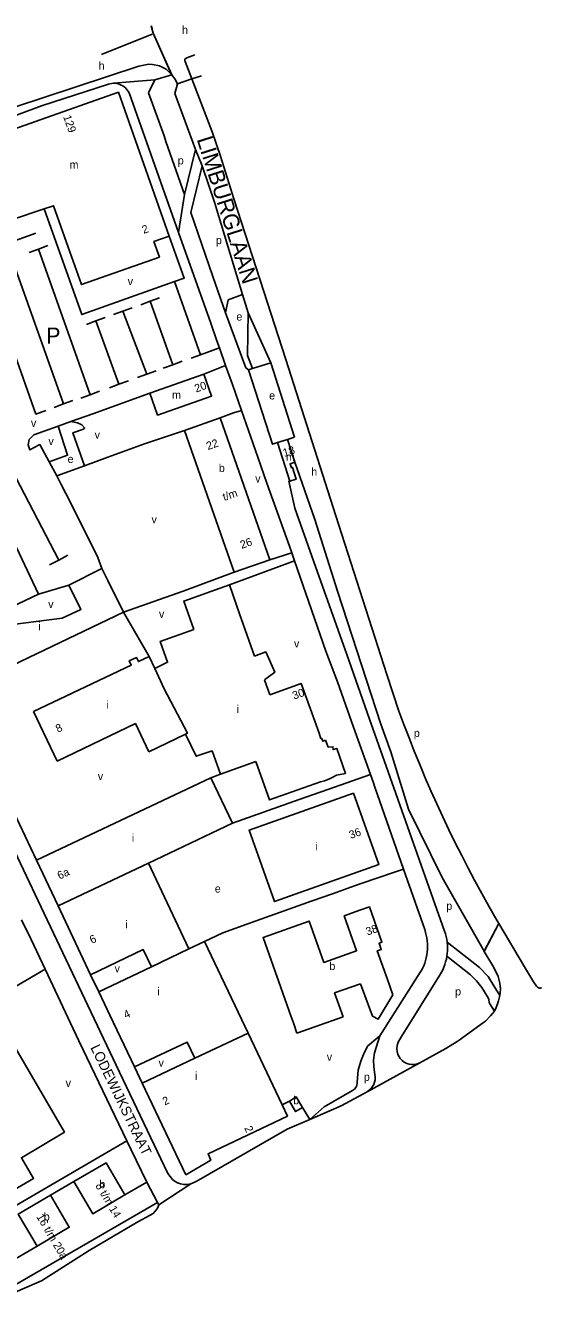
# Model space of a CAD drawing. Extents: x 157699 to 159683, y 381451 to 383293.
# Drawn here: x 159425 to 159683, y 382358 to 382995 of the extents above; entities that cross this region are included whole.
import ezdxf

# ---------------------------------------------------------------- set-up
doc = ezdxf.new("R2010")
doc.units = 0
for name, color, linetype in [('BLT_Basislijn', 7, 'Continuous'), ('BLT_Bebouwing', 7, 'Continuous'), ('BLT_Centroide', 7, 'Continuous'), ('BLT_Huisnummer', 7, 'Continuous'), ('BLT_Huisnummer_reeks', 7, 'Continuous'), ('BLT_Onderverdeling_panden', 7, 'Continuous'), ('BLT_Straatnaam', 7, 'Continuous'), ('BLT_Straatnaam_hoofdweg', 7, 'Continuous'), ('BLT_Tekst_parkeren', 7, 'Continuous'), ('BLT_Vlakafsluiter', 7, 'Continuous')]:
    doc.layers.add(name, color=color, linetype=linetype)

msp = doc.modelspace()

# ---------------------------------------------------------------- linework, layer by layer
at = {"layer": 'BLT_Basislijn'}
for p, q in [((159463.37, 382980.61), (159488.62, 382990.71)), ((159506.02, 382978.92), (159510.05, 382980.42)), ((159505.11, 382977.1), (159508.43, 382968.42)), ((159498.4, 382970.54), (159498.5, 382970.45)), ((159508.43, 382968.42), (159513.39, 382969.92)), ((159508.43, 382968.42), (159518.61, 382941.93)), ((159466.78, 382965.78), (159433.38, 382954.9)), ((159501.88, 382891.65), (159477.18, 382961.35)), ((159486.85, 382961.48), (159494.69, 382939.89)), ((159501.38, 382965.85), (159500.06, 382961.05)), ((159405.59, 382944.56), (159433.38, 382954.9)), ((159494.69, 382939.89), (159495.54, 382937.13)), ((159495.54, 382937.13), (159504.79, 382910.54)), ((159504.79, 382910.54), (159510.28, 382933.07)), ((159507.93, 382901.53), (159513.7, 382924.93)), ((159504.79, 382910.54), (159501.88, 382891.65)), ((159520.31, 382905.05), (159533.82, 382860.61)), ((159507.93, 382901.53), (159519.02, 382869.64)), ((159411.28, 382884.48), (159430.54, 382891.32)), ((159517.97, 382846.23), (159501.88, 382891.65)), ((159431.88, 382883.32), (159436.56, 382885.04)), ((159444.29, 382805.9), (159418.48, 382878.56)), ((159427.2, 382881.61), (159431.88, 382883.32)), ((159457.74, 382810.53), (159431.88, 382883.32)), ((159487.63, 382857.22), (159492.3, 382858.94)), ((159526.75, 382858.01), (159533.82, 382860.61)), ((159533.82, 382860.61), (159536.62, 382851.43)), ((159469.37, 382850.57), (159474.04, 382852.29)), ((159474.04, 382852.29), (159478.72, 382854.01)), ((159485.97, 382820.78), (159474.04, 382852.29)), ((159482.95, 382855.51), (159487.63, 382857.22)), ((159498.93, 382825.49), (159487.63, 382857.22)), ((159526.75, 382858.01), (159525.41, 382851.44)), ((159455.86, 382845.67), (159460.54, 382847.39)), ((159460.54, 382847.39), (159465.21, 382849.1)), ((159472.09, 382815.74), (159460.54, 382847.39)), ((159521.07, 382837.49), (159517.97, 382846.23)), ((159525.41, 382851.44), (159535.47, 382823.87)), ((159512.8, 382830.53), (159522.3, 382834.01)), ((159522.3, 382834.01), (159521.07, 382837.49)), ((159498.93, 382825.49), (159503.61, 382827.21)), ((159508.13, 382828.81), (159512.8, 382830.53)), ((159538.8, 382823.54), (159548.04, 382826.45)), ((159548.04, 382826.45), (159559.89, 382789.26)), ((159481.29, 382819.07), (159485.97, 382820.78)), ((159485.97, 382820.78), (159490.65, 382822.5)), ((159494.26, 382823.78), (159498.93, 382825.49)), ((159514.48, 382820.81), (159525.41, 382825.2)), ((159535.47, 382823.87), (159536.81, 382822.92)), ((159536.81, 382822.92), (159538.8, 382823.54)), ((159467.42, 382814.03), (159472.09, 382815.74)), ((159472.09, 382815.74), (159476.77, 382817.46)), ((159444.29, 382805.9), (159448.97, 382807.61)), ((159453.06, 382808.82), (159457.74, 382810.53)), ((159457.74, 382810.53), (159462.42, 382812.25)), ((159459.06, 382801.01), (159487.53, 382811.25)), ((159439.61, 382804.18), (159444.29, 382805.9)), ((159459.06, 382801.01), (159448.05, 382797.05)), ((159529.37, 382801.41), (159522.67, 382798.96)), ((159529.37, 382801.41), (159533.34, 382802.64)), ((159541.57, 382779.22), (159533.34, 382802.64)), ((159441.63, 382794.74), (159448.05, 382797.05)), ((159504.82, 382792.7), (159484.78, 382785.99)), ((159559.89, 382789.26), (159556.38, 382788.16)), ((159484.78, 382785.99), (159466.45, 382779.24)), ((159414.23, 382781.36), (159441.99, 382727.89)), ((159440.95, 382769.95), (159437.14, 382777.01)), ((159466.45, 382779.24), (159454.82, 382775.01)), ((159546.09, 382766.34), (159541.57, 382779.22)), ((159559.99, 382776.77), (159565.03, 382762.55)), ((159454.82, 382775.01), (159440.95, 382769.95)), ((159547.59, 382762.09), (159546.09, 382766.34)), ((159557.31, 382734.87), (159547.59, 382762.09)), ((159569.57, 382726.97), (159559.93, 382753.88)), ((159580.53, 382750), (159606.02, 382670.74)), ((159547.57, 382728.03), (159558.52, 382731.4)), ((159558.52, 382731.4), (159557.31, 382734.87)), ((159559.87, 382727.51), (159558.52, 382731.4)), ((159441.99, 382727.89), (159437.42, 382725.52)), ((159446.55, 382730.26), (159441.99, 382727.89)), ((159463.57, 382723.62), (159461.58, 382729.21)), ((159559.87, 382727.51), (159527.32, 382715.42)), ((159575.52, 382682.39), (159559.87, 382727.51)), ((159586.01, 382680.69), (159569.57, 382726.97)), ((159529.74, 382721.76), (159504.22, 382712.26)), ((159446.99, 382715.3), (159431.91, 382710.87)), ((159504.22, 382712.26), (159474.33, 382701.74)), ((159603.04, 382645.83), (159581.33, 382712.26)), ((159474.33, 382701.74), (159487.16, 382679.66)), ((159597.38, 382648.39), (159586.01, 382680.69)), ((159606.02, 382670.74), (159612.07, 382652.34)), ((159430.88, 382577.83), (159390.88, 382662.04)), ((159597.8, 382620.63), (159589.42, 382644.27)), ((159518.05, 382619.09), (159522.8, 382620.8)), ((159576.55, 382613.23), (159597.8, 382620.63)), ((159599.29, 382616.45), (159597.8, 382620.63)), ((159599.29, 382616.45), (159600, 382614.42)), ((159562.16, 382608.13), (159576.55, 382613.23)), ((159600, 382614.42), (159614.36, 382573.42)), ((159434.7, 382551.26), (159407.09, 382609.31)), ((159528.82, 382596.4), (159562.16, 382608.13)), ((159593.2, 382566.2), (159609.78, 382571.86)), ((159609.78, 382571.86), (159614.36, 382573.42)), ((159614.36, 382573.42), (159624.96, 382543.14)), ((159634.86, 382542.34), (159623.17, 382575.44)), ((159654.59, 382532.3), (159633.66, 382569.27)), ((159578.81, 382561.1), (159568.61, 382557.48)), ((159568.61, 382557.48), (159535.99, 382545.91)), ((159470.75, 382475.35), (159434.7, 382551.26)), ((159426.63, 382541.3), (159435.12, 382523.3)), ((159654.62, 382532.25), (159654.59, 382532.3)), ((159435.12, 382523.3), (159363.3, 382481.22)), ((159435.12, 382523.3), (159447.81, 382496.36)), ((159622.58, 382521.46), (159602.46, 382490.11)), ((159632.62, 382520.71), (159613.27, 382489.67)), ((159457.92, 382520.61), (159461.96, 382512.07)), ((159447.81, 382496.36), (159451.93, 382487.62)), ((159451.93, 382487.62), (159475.99, 382437.6)), ((159496.48, 382421.26), (159470.75, 382475.35)), ((159479.85, 382474.5), (159483.67, 382466.43)), ((159557.27, 382457.47), (159553.62, 382455.58)), ((159563.81, 382454.25), (159567.46, 382448.29)), ((159449.52, 382417.2), (159437.82, 382410.4)), ((159485.96, 382416.87), (159475.02, 382410.58)), ((159485.96, 382416.87), (159491.41, 382406.79)), ((159491.41, 382406.79), (159410.57, 382359.98)), ((159416.41, 382376.33), (159431.15, 382384.96))]:
    msp.add_line(p, q, dxfattribs=at)
for points in [[(159482.05, 382974.66), (159419.3, 382954.14)], [(159482.05, 382974.66), (159486.94, 382975.68), (159488.85, 382975.57), (159492.4, 382974.84), (159495.62, 382973.17), (159498.4, 382970.54)], [(159506.02, 382978.92), (159505.71, 382978.8), (159505.44, 382978.62), (159505.23, 382978.38), (159505.08, 382978.09), (159505.01, 382977.78), (159505.01, 382977.45), (159505.11, 382977.1)], [(159486.85, 382961.48), (159489.99, 382967.93)], [(159489.99, 382967.93), (159498.5, 382970.45)], [(159498.5, 382970.45), (159500, 382968.4), (159501.38, 382965.85)], [(159466.78, 382965.78), (159467.59, 382965.99), (159469.38, 382966.25)], [(159469.38, 382966.25), (159470.89, 382966.06), (159471.7, 382965.88), (159472.49, 382965.62), (159473.25, 382965.29), (159473.98, 382964.89), (159474.66, 382964.41), (159475.3, 382963.88), (159475.88, 382963.28), (159476.4, 382962.64), (159476.86, 382961.94), (159477.18, 382961.35)], [(159500.06, 382961.05), (159510.28, 382933.07)], [(159518.61, 382941.93), (159522.9, 382929.82), (159529.57, 382908.51)], [(159513.7, 382924.93), (159517, 382915.16), (159519.77, 382906.73), (159520.31, 382905.05)], [(159499.78, 382867.07), (159453.46, 382850.56), (159434.65, 382903.36)], [(159529.57, 382908.51), (159555.53, 382828.13), (159580.53, 382750)], [(159497.26, 382889.83), (159504.68, 382868.8), (159499.78, 382867.07)], [(159409.89, 382875.79), (159407.36, 382866.13), (159430.53, 382800.86), (159435.45, 382802.6)], [(159512.8, 382830.53), (159499.78, 382867.07)], [(159525.41, 382851.44), (159519.02, 382869.64)], [(159536.62, 382851.43), (159536.37, 382830.1), (159538.8, 382823.54)], [(159525.41, 382825.2), (159522.3, 382834.01)], [(159533.34, 382802.64), (159528.76, 382815.68), (159525.41, 382825.2)], [(159551.4, 382786.59), (159548.8, 382785.78), (159536.81, 382822.92)], [(159437.14, 382777.01), (159432.5, 382785.61), (159427.53, 382782.92), (159426.73, 382785.53), (159427.26, 382788.2), (159429.58, 382790.4), (159441.63, 382794.74)], [(159437.14, 382777.01), (159446.4, 382780.26), (159441.63, 382794.74)], [(159448.05, 382797.05), (159451.4, 382796.47), (159453.49, 382795.42), (159454.85, 382794.03), (159454.31, 382793.32), (159449.08, 382791.53), (159454.82, 382775.01)], [(159440.95, 382769.95), (159442.95, 382766.01), (159447.93, 382756.29), (159461.58, 382729.21)], [(159559.93, 382753.88), (159556.96, 382767.23), (159557.53, 382767.31)], [(159581.33, 382712.26), (159569.97, 382748.19), (159565.03, 382762.55)], [(159589.42, 382644.27), (159581.39, 382666.94), (159575.52, 382682.39)], [(159623.17, 382575.44), (159605.72, 382624.81), (159597.38, 382648.39)], [(159612.07, 382652.34), (159614.55, 382645.63), (159617.11, 382638.94), (159619.74, 382632.28), (159622.44, 382625.65), (159625.22, 382619.05), (159628.07, 382612.49), (159631, 382605.95), (159634, 382599.45), (159637.07, 382592.98), (159640.21, 382586.55), (159643.42, 382580.15), (159646.71, 382573.79), (159650.06, 382567.47), (159653.49, 382561.18), (159656.99, 382554.94), (159660.55, 382548.73), (159662.05, 382546.18)], [(159603.04, 382645.83), (159608.08, 382632.06), (159616.91, 382603.37), (159633.66, 382569.27)], [(159578.81, 382561.1), (159589.78, 382564.99), (159593.2, 382566.2)], [(159423.39, 382547.98), (159426.53, 382541.52), (159426.63, 382541.3)], [(159662.05, 382546.18), (159662.08, 382546.13)], [(159535.99, 382545.91), (159524.04, 382541.61), (159514.9, 382537.27)], [(159624.96, 382543.14), (159625.39, 382541.78), (159625.75, 382540.4), (159626.02, 382539.01), (159626.22, 382537.6), (159626.34, 382536.18), (159626.38, 382534.76), (159626.34, 382533.34), (159626.22, 382531.92), (159626.02, 382530.51), (159625.74, 382529.12), (159625.38, 382527.74), (159624.94, 382526.39), (159624.43, 382525.06), (159623.85, 382523.76), (159623.19, 382522.5), (159622.58, 382521.46)], [(159634.86, 382542.34), (159635.3, 382540.99), (159635.67, 382539.63), (159635.96, 382538.25), (159636.18, 382536.79)], [(159662.08, 382546.13), (159674.84, 382524.59), (159679.31, 382517.12), (159680.82, 382514.9), (159681.29, 382514.35), (159681.88, 382514.03), (159682.25, 382513.94), (159682.6, 382513.92), (159682.99, 382513.97), (159683.35, 382514.09)], [(159636.18, 382536.79), (159636.3, 382535.45), (159636.35, 382534.04), (159636.32, 382532.62), (159636.21, 382531.22), (159636.04, 382529.91)], [(159662.51, 382510.28), (159659.57, 382515.08), (159656.7, 382519.77), (159652.36, 382524.27), (159636.18, 382536.79)], [(159636.04, 382529.91), (159635.76, 382528.43), (159635.41, 382527.06), (159634.99, 382525.71), (159634.49, 382524.39), (159633.92, 382523.1), (159633.28, 382521.85), (159632.62, 382520.71)], [(159636.04, 382529.91), (159647.87, 382520.51), (159650.89, 382517.54), (159653.44, 382514.28), (159656.72, 382508.99), (159656.99, 382508.24), (159657.23, 382506.76), (159657.5, 382506), (159659.77, 382502.32)], [(159662.51, 382510.28), (159662.71, 382511.61), (159662.79, 382513.53), (159662.48, 382516.38), (159661.67, 382519.66), (159659.46, 382524.22), (159654.62, 382532.25)], [(159659.77, 382502.32), (159660.71, 382504.26), (159661.22, 382505.58), (159661.87, 382507.5), (159662.51, 382510.28)], [(159622.52, 382476.54), (159635.53, 382483.76), (159641.17, 382487.18), (159642.2, 382487.86), (159654.33, 382496.77), (159655.26, 382497.46), (159657.87, 382499.98), (159659.77, 382502.32)], [(159602.46, 382490.11), (159596.36, 382484.83), (159594.3, 382480.76), (159592.93, 382477.33), (159591.73, 382472.88), (159591.3, 382468.98), (159591.15, 382466.55), (159590.96, 382465.23), (159590.48, 382464.19), (159589.78, 382463.35), (159588.85, 382462.69), (159574.67, 382454.49), (159567.46, 382448.29)], [(159596.12, 382462.1), (159597.15, 382462.81), (159598.09, 382463.69), (159598.89, 382464.73), (159599.48, 382465.8), (159599.89, 382466.91), (159600.15, 382468.08), (159600.22, 382469.56), (159600.08, 382470.77), (159599.46, 382474.48), (159599.37, 382477.93), (159599.9, 382481.49), (159602.46, 382490.11)], [(159622.52, 382476.54), (159621.19, 382476), (159619.88, 382475.72), (159618.36, 382475.68), (159617.23, 382475.84), (159615.98, 382476.23), (159614.73, 382476.87), (159613.62, 382477.72), (159612.73, 382478.7), (159612.11, 382479.62), (159611.56, 382480.76), (159611.16, 382482.14), (159611, 382483.63), (159611.13, 382485.18), (159611.63, 382486.88), (159612.27, 382488.12), (159613.27, 382489.67)], [(159596.12, 382462.1), (159583.18, 382455.03), (159567.46, 382448.29)], [(159567.46, 382448.29), (159556.18, 382443.46), (159510.68, 382417.2), (159507.99, 382416.03)], [(159475.99, 382437.6), (159414.02, 382401.4)], [(159475.99, 382437.6), (159478.04, 382433.33), (159485.96, 382416.87)], [(159507.99, 382416.03), (159506.06, 382415.72), (159504.61, 382415.73), (159502.85, 382416.03), (159501.29, 382416.59), (159500.14, 382417.2), (159498.77, 382418.31), (159496.48, 382421.26)], [(159491.93, 382405.55), (159491.41, 382406.79)], [(159410.57, 382359.98), (159411.58, 382358.24), (159433.32, 382367.59), (159457.14, 382382.69), (159481.58, 382397.01), (159487.75, 382400.41), (159489.13, 382401.27), (159490.41, 382402.52), (159491.35, 382403.99), (159491.93, 382405.55)]]:
    msp.add_lwpolyline(points, dxfattribs=at)
at = {"layer": 'BLT_Bebouwing'}
for p, q in [((159471.87, 382961.72), (159405.77, 382938.41)), ((159418.86, 382898.09), (159434.65, 382903.36)), ((159504.82, 382792.7), (159522.67, 382798.96)), ((159522.67, 382798.96), (159547.57, 382728.03)), ((159529.74, 382721.76), (159504.82, 382792.7)), ((159551.4, 382786.59), (159556.38, 382788.16)), ((159559.99, 382776.77), (159556.38, 382788.16)), ((159551.4, 382786.59), (159557.53, 382767.31)), ((159547.57, 382728.03), (159529.74, 382721.76)), ((159463.57, 382723.62), (159446.99, 382715.3)), ((159466.48, 382717.72), (159463.57, 382723.62)), ((159474.33, 382701.74), (159466.48, 382717.72)), ((159474.33, 382701.74), (159390.88, 382662.04)), ((159441.15, 382627.42), (159429.3, 382652.15)), ((159576.62, 382634.29), (159575.26, 382637.76)), ((159518.05, 382619.09), (159430.88, 382577.83)), ((159486.85, 382576.3), (159528.82, 382596.4)), ((159441.7, 382554.99), (159430.88, 382577.83)), ((159507.08, 382533.56), (159486.85, 382576.3)), ((159457.92, 382520.61), (159441.7, 382554.99)), ((159514.9, 382537.27), (159507.08, 382533.56)), ((159536.63, 382491.43), (159514.9, 382537.27)), ((159488.32, 382524.51), (159461.96, 382512.07)), ((159606.13, 382518.71), (159608.97, 382510.54)), ((159584.19, 382499.58), (159561.08, 382491.41)), ((159536.63, 382491.43), (159553.62, 382455.58)), ((159510.04, 382478.82), (159483.67, 382466.43))]:
    msp.add_line(p, q, dxfattribs=at)
for points in [[(159471.87, 382961.72), (159497.26, 382889.83)], [(159434.65, 382903.36), (159439.41, 382904.95), (159446.66, 382884.3)], [(159446.66, 382884.3), (159453.31, 382865.56), (159492.34, 382879.3), (159489.58, 382887.12), (159497.26, 382889.83)], [(159514.48, 382820.81), (159518.35, 382809.87), (159491.37, 382800.32), (159487.53, 382811.25)], [(159487.53, 382811.25), (159514.48, 382820.81)], [(159557.53, 382767.31), (159560.62, 382768.28), (159558.77, 382774.19), (159558.28, 382774.03), (159557.64, 382776), (159559.99, 382776.77)], [(159403.79, 382769.82), (159431.91, 382710.87)], [(159446.99, 382715.3), (159453.07, 382703.17), (159443.72, 382698.76), (159412.28, 382694.86), (159382.07, 382680.52)], [(159527.32, 382715.42), (159504.43, 382707.37), (159509.43, 382693.17)], [(159532.37, 382701.07), (159527.32, 382715.42)], [(159431.91, 382710.87), (159379.52, 382685.92)], [(159539.82, 382679.91), (159532.37, 382701.07)], [(159509.43, 382693.17), (159492.69, 382687.24), (159496.38, 382676.77), (159489.99, 382673.73)], [(159544.86, 382667.98), (159550, 382671.81), (159545.57, 382681.93), (159539.82, 382679.91)], [(159429.3, 382652.15), (159478.23, 382675.41), (159477.26, 382677.43), (159480.86, 382679.13), (159481.81, 382677.11), (159487.16, 382679.66)], [(159487.16, 382679.66), (159489.99, 382673.73)], [(159547.47, 382660.57), (159544.86, 382667.98)], [(159567.76, 382653.37), (159563.18, 382666.09), (159547.47, 382660.57)], [(159572.96, 382638.58), (159572.11, 382641.29), (159567.76, 382653.37)], [(159441.15, 382627.42), (159480.27, 382646.17), (159487.07, 382632.08)], [(159487.07, 382632.08), (159505.42, 382640.9)], [(159505.42, 382640.9), (159510.73, 382629.78), (159518.61, 382632.5), (159522.8, 382620.8)], [(159575.26, 382637.76), (159574.01, 382637.28), (159573.43, 382638.74), (159572.96, 382638.58)], [(159540.55, 382627.22), (159547.42, 382607.99), (159572.77, 382617.05), (159574.81, 382617.48), (159576.93, 382618.33), (159579.08, 382619.31), (159580.76, 382620.41), (159585.3, 382621.25), (159580.98, 382633.68), (159579.17, 382633.11), (159579.01, 382634.54), (159576.62, 382634.29)], [(159522.8, 382620.8), (159540.55, 382627.22)], [(159528.82, 382596.4), (159518.05, 382619.09)], [(159558.07, 382500), (159544.16, 382539.24), (159567.15, 382547.39), (159574.46, 382526.78), (159590.91, 382532.61), (159584.73, 382550.03), (159592.56, 382552.81), (159597.28, 382554.48), (159603.53, 382536.85), (159602.11, 382536.35), (159603.22, 382533.22), (159601.24, 382532.51), (159606.13, 382518.71)], [(159457.92, 382520.61), (159484.26, 382533.14), (159488.32, 382524.51)], [(159584.19, 382499.58), (159579.89, 382511.49), (159592.9, 382516.1)], [(159592.9, 382516.1), (159598.81, 382499.87), (159601.62, 382498.34), (159608.97, 382510.54)], [(159479.85, 382474.5), (159467.75, 382500), (159461.96, 382512.07)], [(159407.2, 382405.92), (159429.35, 382418.76), (159423.32, 382429.1), (159444.77, 382441.93), (159409.29, 382502.56), (159365.67, 382477.11)], [(159561.08, 382491.41), (159559.43, 382496.13), (159558.07, 382500)], [(159479.85, 382474.5), (159506.19, 382486.93), (159510.04, 382478.82)], [(159483.67, 382466.43), (159505.55, 382420.58)], [(159557.27, 382457.47), (159560.72, 382459.5), (159563.81, 382454.25)], [(159563.81, 382454.25), (159560.36, 382452.22), (159557.27, 382457.47)], [(159553.62, 382455.58), (159556.28, 382449.97), (159516.62, 382431), (159518.06, 382427.96), (159505.55, 382420.58)], [(159475.02, 382410.58), (159465.6, 382426.64), (159449.52, 382417.2)], [(159449.52, 382417.2), (159458.95, 382401.14), (159475.02, 382410.58)], [(159437.82, 382410.4), (159421.75, 382400.96), (159431.15, 382384.96)], [(159431.15, 382384.96), (159447.25, 382394.35), (159437.82, 382410.4)]]:
    msp.add_lwpolyline(points, dxfattribs=at)
msp.add_lwpolyline([(159589.26, 382611.36), (159537.22, 382592.89), (159549.9, 382557.16), (159601.96, 382575.67)], close=True, dxfattribs=at)
at = {"layer": 'BLT_Onderverdeling_panden'}
for p, q in [((159489.99, 382673.73), (159494.76, 382663.58)), ((159486.85, 382576.3), (159441.7, 382554.99)), ((159507.08, 382533.56), (159488.32, 382524.51)), ((159510.04, 382478.82), (159536.63, 382491.43))]:
    msp.add_line(p, q, dxfattribs=at)
msp.add_lwpolyline([(159494.76, 382663.58), (159506.38, 382641.36), (159505.42, 382640.9)], dxfattribs=at)
at = {"layer": 'BLT_Vlakafsluiter'}
for p, q in [((159488.26, 382994.93), (159489.19, 382991.22)), ((159488.31, 382994.94), (159489.24, 382991.24)), ((159489.19, 382991.22), (159498.4, 382970.54)), ((159489.24, 382991.24), (159498.5, 382970.45)), ((159469.38, 382966.25), (159489.99, 382967.93)), ((159508.43, 382968.42), (159501.38, 382965.85)), ((159510.28, 382933.07), (159513.7, 382924.93)), ((159536.62, 382851.43), (159548.04, 382826.45)), ((159654.59, 382532.3), (159662.05, 382546.18)), ((159654.62, 382532.25), (159662.08, 382546.13)), ((159596.12, 382462.1), (159622.52, 382476.54)), ((159507.99, 382416.03), (159491.93, 382405.55))]:
    msp.add_line(p, q, dxfattribs=at)

# ---------------------------------------------------------------- texts
at = {"layer": 'BLT_Centroide'}
for s, p in [('h', (159503.59, 382990.87)), ('h', (159461.9, 382972.97)), ('p', (159501.48, 382925.62)), ('m', (159447.38, 382923.5)), ('p', (159520.56, 382885.78)), ('v', (159476.46, 382865.29)), ('e', (159530.77, 382847.58)), ('m', (159498.59, 382808.46)), ('e', (159547.16, 382808.16)), ('v', (159428.06, 382794.43)), ('v', (159436.81, 382785.37)), ('v', (159459.92, 382788.55)), ('e', (159446.4, 382776.38)), ('b', (159522.01, 382771.89)), ('m', (159555.51, 382777.49)), ('v', (159540.19, 382766.63)), ('h', (159568.21, 382770.02)), ('v', (159488.35, 382746.19)), ('v', (159436.71, 382703.91)), ('v', (159492.08, 382698.96)), ('i', (159431.8, 382692.81)), ('v', (159559.59, 382684.21)), ('i', (159465.85, 382653.53)), ('i', (159530.95, 382651.38)), ('p', (159619.5, 382639.41)), ('v', (159461.5, 382617.89)), ('i', (159478.49, 382587.03)), ('i', (159570.15, 382582.8)), ('e', (159519.98, 382561.65)), ('p', (159635.72, 382553.02)), ('i', (159475.23, 382543.77)), ('b', (159577.28, 382522.94)), ('v', (159469.9, 382521.78)), ('i', (159491.3, 382510.24)), ('p', (159640.14, 382510.24)), ('v', (159491.86, 382474.64)), ('v', (159575.98, 382477.56)), ('i', (159510.03, 382468.03)), ('p', (159594.52, 382467.54)), ('v', (159445.43, 382464.49)), ('b', (159559.2, 382455.86)), ('b', (159462.27, 382413.88)), ('b', (159434.48, 382397.69))]:
    msp.add_text(s, height=4, dxfattribs=at).set_placement(p)
at = {"layer": 'BLT_Huisnummer'}
for s, rotation, p in [('20', 19.44709, (159510.66, 382811.57)), ('18', 17.40992, (159554.73, 382779.43)), ('30', 19.28412, (159559.6, 382658.1)), ('8', 25.35094, (159441.56, 382641.48)), ('36', 19.5232, (159587.93, 382588.43)), ('6a', 25.35094, (159442.4, 382568.09)), ('6', 25.35094, (159458.55, 382535.98)), ('38', 19.5232, (159596.3, 382540.12)), ('4', 25.35094, (159475.5, 382498.47))]:
    msp.add_text(s, height=4, rotation=rotation, dxfattribs=at).set_placement(p)
at = {"layer": 'BLT_Huisnummer_reeks'}
for s, rotation, p in [('129', 289.40767, (159444.12, 382949.52)), ('2', 19.40778, (159484.42, 382890.9)), ('22', 19.44709, (159516.56, 382782.8)), ('t/m', 19.44709, (159524.74, 382757.36)), ('26', 19.44709, (159533.47, 382733.42)), ('2', 25.07765, (159494.96, 382455.22)), ('2', 295.07765, (159534.63, 382443.96)), ('8 t/m 14', 300.56541, (159460.14, 382415.21)), ('16 t/m 20a', 300.42637, (159430.64, 382399.66))]:
    msp.add_text(s, height=4, rotation=rotation, dxfattribs=at).set_placement(p)
at = {"layer": 'BLT_Straatnaam'}
msp.add_text('LODEWIJKSTRAAT', height=5, rotation=295.83973, dxfattribs=at).set_placement((159457.69, 382484.21))
at = {"layer": 'BLT_Straatnaam_hoofdweg'}
msp.add_text('LIMBURGLAAN', height=8, rotation=287.68654, dxfattribs=at).set_placement((159510.88, 382938.26))
at = {"layer": 'BLT_Tekst_parkeren'}
msp.add_text('P', height=8, dxfattribs=at).set_placement((159435.67, 382836.11))

doc.saveas('drawing.dxf')
